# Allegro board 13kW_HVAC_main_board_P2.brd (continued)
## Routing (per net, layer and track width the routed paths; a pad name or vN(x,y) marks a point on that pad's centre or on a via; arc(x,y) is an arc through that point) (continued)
IPH_V+: length 102.6
  I_SAMPLING05 w0.508: v1(58.77,58.8) 58.7,59.02 59.76,61.54 59.76,70.92 55.07,80.27 39.65,87.22 36.92,93.59 36.84,96.22 38,98.54 43.02,102.75 46.78,105.81 46.85,105.88 50.89,111.63 50.89,117.12 55.11,121.33 66.56,121.33 70.63,125.39 J1.25
  BOTTOM w0.508: v1(58.77,58.8) C14.1 R41.2
IPH_W+: length 131
  TOP w0.381: v1(84.72,120.72) 84.64,120.81 84.64,120.83 82.28,123.19 77.24,123.19 73.24,127.18 73.24,128.77 v1(73.37,128.9)
  VCC02 w0.381: J1.22 65.76,129.23 67.6,131.07 71.95,131.07 73.24,129.77 73.24,129.03 v1(73.37,128.9)
  GND03 w0.508: v1(93.64,60.45) 93.53,61.28 88.96,64.91 88.73,67.24 92.92,75.63 95.53,78.23 v1(97.75,78.23)
  PWM04 w0.508: v1(84.72,120.72) 85.89,121.89 108.38,121.89 116.04,114.23 116.04,99.06 98.64,81.66 98.64,78.74 98.14,78.23 v1(97.75,78.23)
  BOTTOM w0.508: R85.1 C16.1 v1(93.64,60.45)
IU+: length 58.8
  BOTTOM w0.508: U3.12 74.64,123.91 C24.1 74.79,124.23 75.4,124.84 75.4,129.72 72.92,132.2 39.91,132.2 37.56,129.85 37.56,125.77 38.6,124.72 40.72,124.72 J1.3
IU-: length 49.5
  BOTTOM w0.508: R36.2 73.11,125.75 C24.2 74.64,126.07 74.64,129.41 72.61,131.44 40.22,131.44 38.32,129.54 38.32,126.08 38.92,125.48 39.64,125.48 40.15,125.99 J1.1
IU_OCP: length 9.6
  BOTTOM w0.508: R65.2 78.96,126.3 78.96,127.38 78.45,127.88 76.93,127.88 76.16,127.12 76.16,122.35 U3.13
IV+: length 132.2
  I_SAMPLING05 w0.508: J1.7 45.69,124.96 43.85,124.96 41.12,123.71 34.68,115.35 31.95,111.64 30.32,110.89 27.8,110.92 25.76,110.94 18.93,111.03 17.12,110.49 15.28,109.92 10.55,102.48 9.78,100.55 3.76,84.27 2.17,71.53 3,63.08 5.29,53.09 10.51,47.87 13.45,47.87 v1(17.36,48)
  BOTTOM w0.508: v1(17.36,48) 16.98,47.37 19.52,40.25 23.33,38.48 24.86,39.24 25.11,40 C23.1 25.87,41.02 26.13,41.52 U1.12
IV-: length 125.3
  I_SAMPLING05 w0.508: v1(18.13,46.99) 10.25,46.99 4.5,52.74 2.32,62.25 1.4,71.54 3.01,84.45 9.87,102.99 14.65,110.52 18.76,111.8 27.5,111.68 30.06,111.76 31.49,112.31 34.07,115.81 40.47,124.12 40.61,124.32 43.69,125.73 44.6,125.73 45.15,126.19 J1.5
  BOTTOM w0.508: v1(18.13,46.99) 20.28,41.02 21.3,40.51 R37.2
  BOTTOM w0.762: C23.2 R37.2
IV_OCP: length 9.3
  BOTTOM w0.508: U1.13 25.36,43.05 24.35,43.05 21.55,41.78 20.79,42.03 20.28,43.3 20.54,44.06 R64.2
IW+: length 163.4
  I_SAMPLING05 w0.508: v1(132.17,44.19) 132.34,46.15 132.32,46.83 132.91,47.91 135.43,49.45 137.92,54.75 138.13,55.45 139.57,67.51 137.17,86.28 133.76,96.96 133.41,97.71 130.93,102.36 125.69,110.78 122.94,114.35 119.19,118.88 112.37,124.88 109.44,127.46 104.85,130.55 100.33,130.55 99.57,131.31 90.07,131.32 75.85,131.32 74.97,132.2 54.89,132.2 54.12,131.43 54.12,128.44 52.85,127.17 J1.11
  BOTTOM w0.508: v1(132.17,44.19) 132.25,44.22 130.52,45.08 130.27,45.59 C39.1 U5.12
IW-: length 161.1
  I_SAMPLING05 w0.508: J1.9 50.38,126.69 51.58,127.88 51.58,129.97 54.57,132.96 75.28,132.96 76.16,132.08 90.07,132.08 99.06,132.07 100.04,132.07 100.79,131.31 105.09,131.31 110.67,127.55 119.74,119.41 125.91,111.95 133.93,98.94 137.92,86.45 140.43,68.41 139.64,60.36 138.97,55.24 136.07,48.61 133.86,47.6 v1(133.44,46.48)
  BOTTOM w0.508: C39.2 R143.2 v1(133.44,46.48)
IW_OCP: length 8.7
  BOTTOM w0.508: U5.13 128.74,44.83 131.64,43.49 131.94,42.78 131.28,41.28 130.27,41.02 R78.2
NETC4_2: length 10.3
  TOP w0.508: v1(61.94,38.22) PAD19.1
  BOTTOM w0.762: R55.2 R31.2 C4.2 66.37,40.24 Q5.6 v1(61.94,38.22)
  vias: v1(59.54,37.38) v1(59.92,36.62) v1(60.45,37.83) v1(60.83,37.07)
NETC5_2: length 10.2
  TOP w0.508: PAD20.1 v1(108.93,76.58)
  BOTTOM w0.762: R54.2 R30.2 C5.2 Q4.6 v1(108.93,76.58)
  vias: v1(109.74,75.13) v1(110.11,75.93) v1(110.76,74.54) v1(111.14,75.35)
NETC6_2: length 10
  TOP w0.762: v1(56.12,91.96) 56.18,92.39 v1(55.46,93.34)
  BOTTOM w0.762: R56.2 55.97,84.04 R34.2 56,85.75 C6.2 56.16,87.29 Q6.6 56.12,90.17 v1(56.12,91.96)
  vias: v1(55.46,94.23) v1(56.35,94.23) v1(56.35,93.34)
NETC7_1: length 55.2
  TOP w0.508: 46.48,70.81 46.14,70.92 PAD3.1 ; v1(38.7,17.39) 37.38,16.08 R1.2
  PWM04 w0.127: 88.06,47.9 87.63,47.9 88.06,47.9 ; 88.06,47.9 C9.1
  PWM04 w0.508: v1(38.7,17.39) 42.26,17.39 43.53,18.66 75.08,18.66 C7.1
  BOTTOM w0.508: Q2.9 44.45,78.09
  vias: v1(40.8,78.06) v1(41.09,77.37) v1(41.7,76.8) v1(42.21,75.72) v1(42.35,77.11) v1(42.65,74.72) v1(42.86,76.03) v1(43.1,73.71) v1(43.3,75.03) v1(43.49,76.3) v1(43.54,72.71) v1(43.75,74.02) v1(43.94,75.3) v1(43.93,71.89) v1(44.14,79.31) v1(44.14,76.62) v1(44.19,73.02) v1(44.25,78.01) v1(44.37,71.02) v1(44.46,74.37) v1(44.58,75.62) v1(44.58,72.21) v1(44.76,76.93) v1(44.81,70.02) v1(44.91,73.37) v1(45.05,71.27) v1(45.21,75.93) v1(45.25,74.75) v1(45.29,72.56) v1(45.32,68.94) v1(45.46,70.33) v1(45.69,73.75) v1(45.76,71.62) v1(45.77,67.94) v1(45.97,69.25) v1(46.08,72.94) v1(46.09,70.65) v1(46.28,66.85) v1(46.42,68.25) v1(46.55,72) v1(46.62,74.65) v1(46.6,69.5) v1(46.74,70.96) v1(46.73,65.85) v1(46.93,67.16) v1(47.07,73.65) v1(47.04,68.5) v1(47.24,69.81) v1(47.25,64.76) v1(47.36,71.27) v1(47.38,66.16) v1(47.53,75.11) v1(47.59,72.57) v1(47.69,68.81) v1(47.69,63.76) v1(47.87,70.12) v1(47.97,74.11) v1(47.9,65.07) v1(48.03,71.57) v1(48.31,69.12) v1(48.34,64.07) v1(48.49,73.03) v1(48.56,70.55) v1(48.52,65.32) v1(48.74,74.45) v1(48.94,72.03) v1(48.97,64.32) v1(49.01,69.55) v1(49.17,65.63) v1(49.26,73.38) v1(49.34,74.7) v1(49.39,68.74) v1(49.47,71.01) v1(49.61,64.63) v1(49.71,72.38) v1(49.79,65.94) v1(49.84,67.74) v1(49.91,70.01) v1(50.17,73.84) v1(50.23,71.36) v1(50.25,66.9) v1(50.3,69.2) v1(50.61,72.84) v1(50.68,70.36) v1(50.74,68.2) v1(50.7,65.9) v1(51.06,69.54) v1(51.14,71.82) v1(51.16,67.36) v1(51.59,70.82) v1(51.51,68.54) v1(51.6,66.36) v1(51.97,70) v1(51.92,67.7) v1(52.37,66.7) v1(52.42,69) v1(52.83,68.16) v1(53.28,67.16) v1(53.36,69.37) v1(53.8,68.37) v1(54.26,69.83) v1(54.21,67.53) v1(54.71,68.83) v1(55.03,70.17) v1(55.12,67.99) v1(55.48,69.17) v1(55.89,68.33) v1(55.94,70.63) v1(56.38,69.63) v1(56.8,68.79) v1(82.04,9.19) v1(82.04,7.92) v1(82.07,6.81) v1(82.07,5.54) v1(82.07,4.27) v1(82.03,3.39) v1(83.21,9.19) v1(83.21,7.92) v1(83.24,6.81) v1(83.24,5.54) v1(83.24,4.27) v1(83.2,3.39) v1(84.45,14.92) v1(84.47,13.97) v1(84.47,12.7) v1(84.47,11.43) v1(84.41,10.42) v1(84.41,9.15) v1(84.41,7.88) v1(84.44,6.77) v1(84.44,5.5) v1(84.44,4.23) v1(84.4,3.36) v1(85.05,94.27) v1(85.06,93.55) v1(85.02,92.88) v1(85.03,92.16) v1(85.05,91.46) v1(85.68,10.42) v1(85.68,9.15) v1(85.68,7.88) v1(85.67,3.36) v1(85.72,90.64) v1(85.75,89.63) v1(85.74,88.79) v1(85.78,87.77) v1(85.71,86.77) v1(85.74,85.75) v1(85.73,84.91) v1(85.76,83.89) v1(85.72,14.92) v1(86.15,94.25) v1(86.16,93.53) v1(86.11,92.86) v1(86.12,92.14) v1(86.14,91.44) v1(86.65,86.78) v1(86.68,85.77) v1(86.67,84.93) v1(86.7,83.91) v1(86.82,90.63) v1(86.85,89.61) v1(86.84,88.77) v1(86.87,87.75) v1(86.93,50.34) v1(86.96,49.5) v1(86.96,10.41) v1(86.96,9.14) v1(86.96,7.87) v1(86.94,3.36) v1(87,14.91) v1(87.35,94.26) v1(87.36,93.54) v1(87.4,51.44) v1(87.75,90.64) v1(87.79,89.63) v1(87.77,88.79) v1(87.74,86.77) v1(87.78,85.75) v1(87.76,84.91) v1(87.81,87.77) v1(87.8,83.89) v1(87.82,50.07) v1(88.24,51.14) v1(88.27,14.91) v1(88.25,13.91) v1(88.25,12.64) v1(88.25,11.37) v1(88.23,10.41) v1(88.23,9.14) v1(88.23,7.87) v1(88.2,6.9) v1(88.2,5.63) v1(88.2,4.36) v1(88.21,3.35) v1(88.44,94.24) v1(88.46,93.52) v1(88.76,49.69) v1(88.85,90.63) v1(88.88,89.61) v1(88.87,88.77) v1(88.9,87.75) v1(89.18,50.75) v1(89.45,13.83) v1(89.45,12.56) v1(89.45,11.29) v1(89.42,6.9) v1(89.42,5.63) v1(89.42,4.36) v1(89.54,14.91) v1(89.5,10.41) v1(89.5,9.14) v1(89.5,7.87) v1(89.65,94.25) v1(89.66,93.53) v1(89.62,92.86) v1(89.63,92.14) v1(89.65,91.44) v1(89.67,49.17) v1(89.75,90.63) v1(89.78,89.62) v1(89.77,88.77) v1(89.8,87.76) v1(90.1,50.24) v1(90.54,46.33) v1(90.62,48.79) v1(90.75,94.23) v1(90.76,93.51) v1(90.71,92.84) v1(90.73,92.12) v1(90.74,91.42) v1(90.77,10.41) v1(90.77,9.14) v1(90.77,7.87) v1(90.84,90.61) v1(90.88,89.6) v1(90.86,88.76) v1(90.81,14.91) v1(90.9,87.74) v1(90.96,47.4) v1(91.04,49.86) v1(91.42,48.39) v1(91.48,45.95) v1(91.89,49.48) v1(91.87,10.44) v1(91.87,9.17) v1(91.87,7.9) v1(91.94,94.23) v1(91.95,93.51) v1(91.97,92.81) v1(91.98,92.09) v1(91.99,90.66) v1(91.9,47.01) v1(92,91.39) v1(92.02,89.64) v1(92.01,88.8) v1(92.04,87.79) v1(92.36,48.01) v1(92.4,45.43) v1(92.83,49.1) v1(92.82,46.5) v1(93.04,94.22) v1(93.05,93.5) v1(93.08,90.64) v1(93.17,92.37) v1(93.14,91.54) v1(93.12,89.63) v1(93.1,88.78) v1(93.14,87.77) v1(93.28,47.49) v1(93.75,48.59) v1(94.01,94.24) v1(94.02,93.52) v1(94.28,90.66) v1(94.22,47.11) v1(94.36,92.39) v1(94.33,91.55) v1(94.31,89.64) v1(94.3,88.8) v1(94.33,87.79) v1(94.69,48.2) v1(94.91,94.25) v1(94.92,93.53) v1(95.37,90.64) v1(95.39,88.78) v1(95.45,92.37) v1(95.43,91.54) v1(95.4,89.63) v1(96.01,94.23) v1(96.02,93.51) v1(96.25,48.78) v1(96.7,49.69) v1(96.77,46.22) v1(97.11,94.21) v1(97.12,93.49) v1(97.1,92.8) v1(97.11,92.08) v1(97.13,91.38) v1(97.23,47.21) v1(97.41,48.19) v1(97.94,49.24) v1(98.2,94.19) v1(98.22,93.47) v1(98.19,92.78) v1(98.21,92.06) v1(98.22,91.36) v1(99.4,94.19) v1(99.41,93.47) v1(99.42,91.37) v1(100.48,94.19) v1(100.5,93.46) v1(100.51,91.35)
NETC17_2: length 5.3
  TOP w0.762: v2(42.17,90.97) 42.11,91.02 C18.2 C17.2 R66.2
  BOTTOM w0.762: v2(42.17,90.97) U2.1
NETC25_1: length 4.4
  BOTTOM w0.762: U2.2 42.21,92.24 C25.1 40.78,92.18 R69.1 40.71,92.24 R67.2
NETC26_1: length 8.9
  TOP w0.508: C27.1 47.58,94.45 C28.1 C26.1 ; C27.1 49.84,94.45 v1(50.27,94.88) ; C27.1 48.97,96.32 R68.1
  BOTTOM w0.508: U2.5 v1(50.27,94.88)
  BOTTOM w0.762: U2.5 50.18,94.86
NETC30_1: length 19.7
  BOTTOM w0.254: R75.1 116.68,114.7 112.99,114.68 112.44,114.12 112.44,107.81 112.99,107.44 U4.14
  BOTTOM w0.508: U4.10 115.57,112.5 116.33,113.25 116.33,113.25 116.36,113.28 C30.1
  BOTTOM w0.762: R72.2 R75.1 C30.1
NETC32_1: length 1.3
  BOTTOM w0.762: R73.1 C32.1
NETC34_2: length 5.7
  TOP w0.762: R83.2 C34.2 C36.2 v1(68.87,25.95)
  BOTTOM w0.762: v1(68.87,25.95) U7.1
NETC35_1: length 80.2
  TOP w1.016: CN2.1 11.39,88.77 9.87,83.05 7.76,81.14 C35.1
  TOP w1.524: C35.1 CN1.1
  VCC02 w1.27: CN2.1 11.02,86.78 9.52,82.26 C35.1
  PWM04 w1.27: CN1.1 C35.1
  I_SAMPLING05 w1.27: CN1.1 C35.1 9.62,82.93 11.14,88.18 CN2.1
  BOTTOM w1.524: CN2.1 12.92,90.67 9.74,85.47 10,82.42 C35.1 CN1.1
NETC38_1: length 20.1
  I_SAMPLING05 w0.508: v1(117.22,101.2) 117.3,101.97 117.69,102.36 117.69,108.45 118.99,109.75 118.99,110.25 119.85,111.12 v1(119.85,111.25)
  BOTTOM w0.508: v1(119.85,111.25) 119.85,110.33 119.34,109.83 R70.1
  BOTTOM w0.762: v1(117.22,101.2) 117.22,101.97 R81.2 C38.1 C40.1 116.19,106.15 U4.15
NETC48_1: length 5.1
  BOTTOM w0.762: R86.2 R90.1 C48.1 U7.2
NETC49_1: length 8.5
  TOP w0.508: R89.1 60.76,29.77 60.94,29.95 ; C50.1 C51.1 C49.1
  TOP w0.762: v1(61.58,31.87) C50.1 R89.1
  BOTTOM w0.762: v1(61.58,31.87) U7.5
NETC55_2: length 6
  TOP w0.762: v1(113.81,89.56) C56.2 C55.2 R99.2
  BOTTOM w0.762: v1(113.81,89.56) U9.1
NETC58_1: length 15.8
  BOTTOM w0.762: Q7.C R98.2
  BOTTOM w1.016: R98.2 124.3,88.13 122.9,88.64 122.52,90.04 122.77,91.31 C61.1 ; C61.1 C59.1 D6.2 ; C61.1 C58.1
NETC58_2: length 8.9
  TOP w1.016: v1(122.27,94.99) 123.31,94.86 T1.4
  BOTTOM w1.016: v1(122.27,94.99) C58.2 C63.1
NETC60_2: length 10
  TOP w0.508: T1.3 124.93,99.69 125.73,99.69 129.12,101.72 129.25,102.36 127.66,105.24
NETC65_1: length 2.1
  TOP w0.381: U8.3 118.75,109.72
  TOP w0.508: C65.1 R100.2
NETC66_1: length 2.9
  TOP w0.381: U8.5 C66.1 R105.1
NETC68_1: length 4.5
  BOTTOM w0.762: R101.2 R103.1 C68.1 U9.2
NETC70_1: length 7.8
  TOP w0.508: v1(113.78,80.48) 113.71,81.23 C71.1 ; C71.1 C72.1 C70.1 ; C71.1 114.99,81.31 R102.1
  BOTTOM w0.762: v1(113.78,80.48) U9.5
NETC74_1: length 20
  BOTTOM w0.508: U10.10 17.03,83.75 16.08,83.98 C74.1 15.71,84.65 14.52,84.09 R112.1 ; R112.1 R110.2 ; R112.1 14.38,83.92 16.3,79.81 17.2,79.81 22.64,82.77 22.73,83.59 U10.14
NETC77_1: length 12.5
  TOP w0.711: C77.1 102.24,118 R115.2
  TOP w0.762: Q8.C 107.57,118.42 106.9,119.09 v1(103.61,119.09) R115.2
  BOTTOM w0.762: C78.1 103.61,118.18 v1(103.61,119.09) ; C78.1 101.73,117.95 D10.2 ; C78.1 105.13,117.95 C80.1
NETC77_2: length 4.8
  TOP w0.762: T2.4 99.41,114.55 C83.1 C77.2
NETC82_1: length 17.1
  PWM04 w0.508: v1(17.4,87.86) 18.08,88.55 v1(26.44,88.55)
  BOTTOM w0.508: R108.1 v1(17.4,87.86) ; U10.15 22.66,86.76 C84.1 C82.1 R116.2 26.04,89.41 v1(26.44,88.55)
NETC89_1: length 14.2
  I_SAMPLING05 w0.508: v1(102.02,15.81) v1(107.02,12.61)
  BOTTOM w0.508: R121.1 106.03,13.25 106.29,13.25 106.63,13.59 U11.10 ; R121.1 C89.1 ; R121.1 R119.2 v1(107.02,12.61) ; U11.14 v1(102.02,15.81)
NETC93_1: length 18.6
  TOP w0.762: v1(13.65,76.09) Q9.C R126.2
  BOTTOM w0.711: 12.97,69.84 12.2,70.59 D16.2
  BOTTOM w0.762: 12.97,69.84 16.09,69.87 C93.1 ; v1(13.65,76.09) C95.1 ; C95.1 13.43,74.04 13.43,72.51 D16.2 ; C95.1 C97.1
NETC93_2: length 5.4
  TOP w1.27: v1(17.19,66.64) T3.4
  BOTTOM w0.762: C93.2 v1(17.19,66.64) 18.32,67.77 C102.1
NETC96_1: length 24.3
  PWM04 w0.762: v1(100.71,12.42) 100.71,15.11 95.16,17.7 v1(94.66,19.15) 95.44,20.85
  BOTTOM w0.508: v1(94.66,19.15) 95.6,20.95 95.6,20.95 95.9,21.26 96.1,21.33 96.74,21.33 R127.2 C96.1 C99.1 100.49,20.12 102.1,19.27 102.28,18.65 U11.15 ; v1(100.71,12.42) R117.1
NETC104_2: length 258.5
  TOP w1.016: v1(87.47,118.23) 87.51,116.65 89.53,114.71 T2.3 ; T4.3 85.7,24.11 84.17,25.65 83.28,28.32 74.26,37.46 v1(74.26,44.06)
  TOP w1.27: T3.3 v1(13.52,56.89)
  GND03 w1.016: v1(87.47,118.23) 87.47,118.5 87.72,118.76 89.13,120.16 107.63,120.16 111.72,116.07 111.72,102.54 v1(114.26,100)
  PWM04 w1.016: v1(51.27,79.96) 51.15,80.08 49.01,80.08 43.12,85.97 35.02,85.97 32.98,83.94 28.19,83.94 25.1,85.97 22.06,85.85 14.82,81.91 10.96,75.42 10.41,69.12 7.46,66.16 7.46,62.95 8.87,61.54 v1(13.52,56.89)
  BOTTOM w0.762: C104.2 R128.1 73.24,64.92 73.24,63.88 72.93,63.56 R134.2 C110.1 ; 80.75,63.69 77.48,63.69
  BOTTOM w1.016: v1(74.26,44.06) 74.57,44.38 C104.2 75.53,64.96 76.9,64.07 76.96,64 76.99,64 77.48,63.69 ; 80.75,63.69 105.85,88.79 105.86,88.79 111.98,94.92 111.98,97.56 114.26,99.84 v1(114.26,100) ; v1(51.27,79.96) 55.82,79.96 65.88,69.9 65.88,67.31 69.62,63.56 C110.1
NETC108_1: length 2.8
  BOTTOM w0.381: 79.38,67.35 U12.5
  BOTTOM w0.508: C108.1 79.38,67.35
  BOTTOM w0.762: C108.1 R131.1
NETC109_1: length 4.1
  BOTTOM w0.305: 77.18,72.48 U12.3
  BOTTOM w0.508: R129.2 77.18,72.48
  BOTTOM w0.762: R129.2 74.6,73.57 C109.1
NETC110_2: length 3.3
  BOTTOM w0.762: RJ1.2 71.93,66.32 R134.1 C110.2
NETC112_1: length 17.1
  TOP w0.762: Q10.C C113.1 ; C113.1 R138.2 ; C113.1 C114.1 102.83,28.37 102.8,28.45 102.8,28.53 102.69,28.82 102.62,28.85 102.58,28.95 102.57,28.97 102.35,29.1 102.33,29.16 100.88,29.83 99.54,29.92 D22.2 97.65,29.69 96.33,26.92 C112.1
NETC112_2: length 4.7
  TOP w0.762: T4.4 C112.2 C116.1
NETC121_2: length 4.3
  BOTTOM w0.508: 117.18,109.96 R70.2
  BOTTOM w0.762: C121.2 R70.2 ; U4.12 117.18,109.96
NETC122_2: length 3.9
  BOTTOM w0.508: C122.2 17.48,85.53 R108.2 18.81,86.01 19.73,84.03 U10.12
NETC123_2: length 5.4
  BOTTOM w0.254: C123.2 102.47,14.18 103.05,14.57 103.06,14.58 103.07,14.58 103.11,14.61 103.4,14.7 103.71,14.81 104.23,14.81 104.71,14.95 U11.12
  BOTTOM w0.762: R117.2 101.85,14.16 C123.2
NETCN2_5: length 16.3
  I_SAMPLING05 w1.27: L1.4 29.96,89.23 27.1,92.08 22.57,96.02 CN2.5
NETCN2_6: length 29.8
  TOP w0.457: L1.3 19.7,94.66 17.87,94.66 16.2,96.34 CN2.6
  PWM04 w0.457: CN2.6 16.19,96.34 16.5,95.68 18.4,94.46 L1.3
  I_SAMPLING05 w0.457: L1.3 19.7,94.66 17.92,94.66 17.79,94.79 17.77,94.79 16.2,96.36 CN2.6
  BOTTOM w0.457: L1.3 19.7,94.66 17.9,94.66 16.2,96.36 CN2.6
NETCON3_1: length 4.9
  BOTTOM w0.508: CON3.3 38.52,25.47 R4.2
  vias: v1(35.28,45.44) v1(35.86,45.7) v1(35.82,44.28) v1(36.36,43.13) v1(36.43,45.97) v1(36.4,44.55) v1(36.97,44.82) v1(36.93,43.4) v1(36.9,41.11) v1(37.05,46.79) v1(36.99,46.18) v1(37.48,40.04) v1(37.57,45.68) v1(37.53,45.03) v1(37.51,43.67) v1(37.93,41.59) v1(37.99,38.77) v1(37.98,36.03) v1(38.09,47.27) v1(38.07,43.88) v1(38.13,44.48) v1(38.15,31.14) v1(38.49,37.7) v1(38.51,40.52) v1(38.6,46.16) v1(38.64,43.38) v1(38.63,30.1) v1(39.02,39.25) v1(39.02,36.52) v1(39.06,29.13) v1(39.16,44.97) v1(39.1,35.57) v1(39.2,42.18) v1(39.41,31.73) v1(39.52,38.18) v1(39.59,34.53) v1(39.68,43.86) v1(39.78,41.11) v1(39.9,30.69) v1(40.02,36) v1(40.02,33.57) v1(40.19,37.01) v1(40.24,42.66) v1(40.29,39.84) v1(40.33,29.72) v1(40.48,32.34) v1(40.51,34.96) v1(40.75,41.56) v1(40.79,38.77) v1(40.94,34) v1(40.96,31.3) v1(41.31,40.36) v1(41.41,37.58) v1(41.4,30.34) v1(41.75,32.93) v1(41.83,39.26) v1(41.86,29.19) v1(42.23,31.89) v1(42.31,38) v1(42.35,28.15) v1(42.66,30.93) v1(42.78,33.41) v1(42.78,29.62) v1(42.78,27.18) v1(43.27,32.38) v1(43.27,28.58) v1(43.7,31.41) v1(43.7,27.61) v1(44.05,34) v1(44.53,32.97) v1(44.96,32)
NETCON4_1: length 5.5
  TOP w0.762: R5.2 131.41,59.94 CON4.4
  vias: v1(117.33,52.33) v1(117.63,53.44) v1(118.19,54.64) v1(118.13,51.79) v1(118.67,52.96) v1(118.65,52.19) v1(118.7,55.74) v1(119.19,53.34) v1(119.17,51.9) v1(119.26,56.94) v1(119.23,54.15) v1(119.78,58.04) v1(119.74,55.26) v1(119.73,54.49) v1(119.71,53.05) v1(119.75,51.63) v1(120.25,54.2) v1(120.29,52.78) v1(120.34,59.24) v1(120.3,56.45) v1(120.32,51.36) v1(120.74,57.58) v1(120.85,60.34) v1(120.82,53.93) v1(120.86,52.51) v1(121.39,58.79) v1(121.4,53.66) v1(121.5,61.53) v1(121.56,55.86) v1(121.89,59.86) v1(122.01,56.99) v1(122.41,61.11) v1(122.66,58.2) v1(122.6,55.38) v1(123.05,56.51) v1(123.15,59.27) v1(123.45,65.43) v1(123.63,60.54) v1(123.69,57.72) v1(123.93,66.46) v1(124.19,58.79) v1(124.39,67.41) v1(124.51,61.06) v1(124.71,64.84) v1(124.76,59.96) v1(124.99,62.1) v1(125.2,65.87) v1(125.45,63.05) v1(125.43,60.63) v1(125.66,66.82) v1(125.75,64.35) v1(125.79,59.47) v1(125.91,61.67) v1(126.23,65.39) v1(126.37,62.62) v1(126.69,66.34) v1(127.01,63.76) v1(127.5,64.8) v1(127.62,67.28) v1(127.96,65.75) v1(128.1,68.31) v1(128.17,63.34) v1(128.57,69.26) v1(128.54,66.85) v1(128.65,64.37) v1(129.02,67.88) v1(129.12,65.33) v1(129.49,68.84) v1(129.44,62.75) v1(129.92,63.78) v1(130.38,64.74)
NETCON5_1:
  vias: v1(53.79,113.92) v1(53.79,112.9) v1(54.85,113.9) v1(54.85,112.89) v1(55.99,113.9) v1(55.99,112.89) v1(57.13,116.47) v1(57.13,115.07) v1(57.23,113.84) v1(57.23,112.44) v1(57.23,111.3) v1(57.23,109.9) v1(58.18,116.45) v1(58.18,115.05) v1(58.29,113.82) v1(58.29,112.43) v1(58.29,111.28) v1(58.29,109.89) v1(59.33,116.45) v1(59.33,115.05) v1(59.43,113.82) v1(59.43,112.43) v1(59.43,111.28) v1(59.43,109.89) v1(60.04,115.82) v1(60.16,114.55) v1(60.74,113.73) v1(60.74,112.71) v1(61.8,113.71) v1(61.8,112.69) v1(62.94,113.71) v1(62.94,112.69) v1(63.79,112.12) v1(63.78,110.77) v1(63.78,109.77) v1(64.97,112.14) v1(65.13,110.83) v1(65.18,109.91) v1(66.9,109.91) v1(68.23,109.91) v1(69.4,112.22) v1(69.4,110.83) v1(69.44,109.91) v1(69.66,113.37) v1(70.72,110.83) v1(70.77,109.91) v1(71.47,113.64) v1(71.47,113) v1(71.47,112.37) v1(71.47,111.73) v1(71.94,110.83) v1(71.95,109.91) v1(72.74,113.64) v1(72.74,113) v1(72.74,112.37) v1(72.74,111.73) v1(73.26,110.83) v1(73.27,109.91) v1(74.01,113.64) v1(74.01,113) v1(74.01,112.37) v1(74.01,111.73) v1(74.48,110.83)
NETD1_2: length 2.2
  BOTTOM w0.762: R24.1 D1.2
NETD1_2_2: length 2.2
  TOP w0.762: R24_2.1 D1_2.2
NETD2_2: length 2.2
  BOTTOM w0.762: R25.1 D2.2
NETD3_2: length 2.2
  BOTTOM w1.27: R26.1 D3.2
NETD4_1: length 3.5
  TOP w0.762: R140.2 109.49,102.92 108.11,101.54 D4.1
NETD4_2: length 4.5
  TOP w1.016: D5.1 D4.2
NETD6_1: length 7.1
  TOP w1.016: T1.6 v1(132.04,94.61)
  BOTTOM w1.016: D6.1 D8.2 131.2,95.38 v1(132.04,94.61)
NETD7_2: length 6.6
  BOTTOM w0.762: D7.2 R98.1 128.75,85.1 Q7.B
NETD10_1: length 4.6
  TOP w0.762: v1(98.01,119.12) 98.01,118.26 T2.6
  BOTTOM w0.762: v1(98.01,119.12) 98.27,118.98 D10.1 98.27,115.67 D12.2
NETD11_2: length 6
  TOP w0.711: R115.1 105.08,117.29 104.3,116.51 D11.2
  TOP w0.762: R115.1 106.49,118 107.19,117.3 Q8.B
NETD14_1: length 6.8
  TOP w1.016: D14.1 v1(32.43,81.58)
  BOTTOM w0.762: v1(32.43,81.58) 33.11,81.43 34.1,79.35 33.82,78.66 R141.2
NETD14_2: length 3.7
  TOP w1.016: D15.1 40.35,82.82 D14.2
NETD16_1: length 5.2
  TOP w1.27: T3.6 v1(13.05,68.58)
  BOTTOM w0.762: D18.2 13.44,68.58 v1(13.05,68.58) 12.19,67.72 D16.1
NETD17_2: length 3
  TOP w0.762: Q9.B R126.1 D17.2
NETD20_1: length 5.6
  TOP w1.016: D20.1 90.1,36.04 R142.2
NETD20_2: length 3.8
  TOP w1.016: D20.2 89.87,41.11 D21.1
NETD22_1: length 4.5
  TOP w0.762: D22.1 D24.2 T4.6
NETD23_2: length 2.9
  TOP w0.762: Q10.B R138.1 D23.2
NETD26_1: length 1.7
  BOTTOM w1.27: D27.2 D26.1
NETD27_1: length 1.7
  BOTTOM w1.27: D28.2 D27.1
NETPAD8_1:
  vias: v1(28.49,65.41) v1(29.03,64.26) v1(29.52,63.34) v1(30.05,62.18) v1(30.51,61.26) v1(31.33,60.18) v1(31.82,59.2) v1(31.97,66.87) v1(32.06,60.52) v1(32.27,58.16) v1(32.5,65.72) v1(32.5,59.52) v1(32.67,57.15) v1(32.77,67.24) v1(32.99,64.79) v1(33,58.51) v1(33.18,56.04) v1(33.14,50.06) v1(33.21,61.05) v1(33.31,66.09) v1(33.53,63.64) v1(33.67,60.01) v1(33.68,48.91) v1(33.7,57.63) v1(33.74,54.84) v1(33.71,50.33) v1(33.8,65.17) v1(33.99,62.72) v1(34.15,59.04) v1(34.22,56.52) v1(34.26,53.74) v1(34.29,50.59) v1(34.25,49.17) v1(34.21,47.76) v1(34.33,64.02) v1(34.44,61.62) v1(34.6,52.78) v1(34.79,63.09) v1(34.78,55.33) v1(34.79,48.02) v1(34.89,60.58) v1(34.85,58.17) v1(34.87,50.86) v1(34.83,49.44) v1(35,51.83) v1(35.29,54.22) v1(35.34,62.04) v1(35.37,59.61) v1(35.39,57.01) v1(35.36,48.29) v1(35.4,49.71) v1(35.52,50.72) v1(35.64,53.26) v1(35.79,61) v1(35.93,55.86) v1(35.94,48.56) v1(36.08,58.73) v1(36.04,52.31) v1(36.07,49.52) v1(36.27,60.03) v1(36.46,54.71) v1(36.55,51.2) v1(36.59,48.42) v1(36.61,57.58) v1(36.81,53.75) v1(36.98,59.16) v1(37.15,56.43) v1(37.19,52.85) v1(37.11,50.01) v1(37.51,58) v1(37.69,55.28) v1(37.63,48.9) v1(37.72,51.69) v1(38.05,56.85) v1(38.03,54.32) v1(38.26,50.54) v1(38.41,53.41) v1(38.59,55.7) v1(38.8,49.39) v1(38.94,54.74) v1(38.95,52.26) v1(39.31,53.84) v1(39.48,51.11) v1(40.02,49.96) v1(40.69,48.51) v1(41.17,47.48) v1(41.72,46.32) v1(42.2,45.28) v1(42.58,46.78) v1(42.69,44.2) v1(43.07,45.75) v1(43.17,43.17) v1(43.56,44.67) v1(43.66,42.13) v1(44.05,46.22) v1(44.04,43.64) v1(44.06,41.16) v1(44.57,45.13) v1(44.52,42.6) v1(44.92,41.63) v1(45.05,44.1) v1(45.39,38.24) v1(45.45,45.58) v1(45.53,43.06) v1(45.94,44.54) v1(45.93,42.09) v1(45.94,37.08) v1(46.36,41.09) v1(46.31,38.67) v1(46.42,43.5) v1(46.42,36.04) v1(46.82,42.53) v1(46.87,40.09) v1(46.86,37.51) v1(46.94,34.96) v1(47.28,41.52) v1(47.35,39.06) v1(47.34,36.47) v1(47.42,33.92) v1(47.79,40.52) v1(47.83,35.4) v1(47.9,37.89) v1(47.91,32.88) v1(48.27,39.49) v1(48.38,36.86) v1(48.31,34.36) v1(48.45,31.68) v1(48.79,33.33) v1(48.82,38.32) v1(48.91,35.77) v1(48.93,30.65) v1(49.3,37.29) v1(49.39,34.73) v1(49.37,32.11) v1(49.79,36.21) v1(49.87,33.7) v1(49.85,31.08) v1(50.28,35.18) v1(50.41,32.5) v1(50.68,27.28) v1(50.76,34.14) v1(50.9,31.46) v1(51.33,32.92) v1(51.44,30.3) v1(51.56,27.72) v1(51.82,31.89) v1(51.93,29.26) v1(52.36,30.73) v1(52.45,28.17) v1(52.85,29.69) v1(53.33,28.61)
NETPAD10_1:
  vias: v1(105.48,35.89) v1(105.77,36.57) v1(106.16,37.54) v1(106.29,35.58) v1(106.58,36.2) v1(106.7,38.69) v1(106.97,37.16) v1(107.11,39.64) v1(107.57,40.73) v1(107.51,38.31) v1(107.92,39.26) v1(108.08,41.75) v1(108.47,40.31) v1(108.51,42.74) v1(108.73,43.84) v1(108.98,41.33) v1(109.26,44.99) v1(109.41,42.32) v1(109.63,43.42) v1(109.69,39.74) v1(109.8,46.14) v1(110.02,34.64) v1(110.16,44.57) v1(110.2,40.76) v1(110.34,47.29) v1(110.37,35.39) v1(110.63,41.75) v1(110.7,45.72) v1(110.85,48.18) v1(110.85,42.85) v1(110.84,39.2) v1(110.91,36.54) v1(111.24,46.87) v1(111.3,49.05) v1(111.38,44) v1(111.33,40.17) v1(111.45,37.61) v1(111.57,38.86) v1(111.75,47.76) v1(111.78,41.21) v1(111.92,45.15) v1(112,42.31) v1(112.01,39.86) v1(112.2,48.63) v1(112.46,46.3) v1(112.51,43.42) v1(112.51,40.87) v1(112.74,49.78) v1(112.97,47.19) v1(113.07,44.62) v1(113.03,41.83) v1(113.28,50.93) v1(113.42,48.06) v1(113.59,45.72) v1(113.55,42.94) v1(113.68,59.06) v1(113.81,52.08) v1(113.96,49.21) v1(114.09,57.57) v1(114.16,60.1) v1(114.1,46.6) v1(114.11,44.13) v1(114.49,53.53) v1(114.59,58.67) v1(114.5,50.36) v1(114.57,47.52) v1(114.65,61.14) v1(114.6,56.09) v1(114.62,45.24) v1(114.97,54.56) v1(115.07,59.7) v1(115.08,57.12) v1(115.03,51.51) v1(115.09,48.63) v1(115.13,62.06) v1(115.13,46.12) v1(115.55,60.74) v1(115.59,58.19) v1(115.51,55.73) v1(115.61,63.07) v1(115.65,49.82) v1(115.61,47.04) v1(116.05,64.1) v1(116.04,61.67) v1(116.07,59.23) v1(115.99,56.76) v1(116.16,50.93) v1(116.13,48.14) v1(116.53,65.14) v1(116.53,62.64) v1(116.56,60.26) v1(116.5,57.83) v1(116.68,49.34) v1(116.6,47.36) v1(116.97,63.67) v1(116.99,58.86) v1(117.07,66.3) v1(117.05,61.19) v1(117.14,48.51) v1(117.17,47.09) v1(117.2,50.45) v1(117.45,64.71) v1(117.47,59.9) v1(117.55,67.34) v1(117.67,49.66) v1(117.71,48.24) v1(117.75,46.82) v1(117.99,65.88) v1(117.96,60.83) v1(118.06,68.41) v1(118.25,49.39) v1(118.29,47.97) v1(118.33,46.55) v1(118.47,66.91) v1(118.42,64.16) v1(118.55,69.44) v1(118.82,49.12) v1(118.86,47.7) v1(118.97,68.01) v1(118.96,65.32) v1(119.03,70.48) v1(119.34,63.73) v1(119.46,69.05) v1(119.44,66.36) v1(119.4,48.86) v1(119.59,71.7) v1(119.88,64.89) v1(119.94,70.08) v1(120.07,72.74) v1(120.06,67.59) v1(120.36,65.93) v1(120.51,71.27) v1(120.54,68.63) v1(120.61,73.9) v1(120.89,69.64) v1(120.97,67.19) v1(120.99,72.31) v1(121.1,74.94) v1(121.48,70.72) v1(121.45,68.23) v1(121.53,73.47) v1(121.61,76) v1(121.88,69.26) v1(121.96,71.75) v1(122.02,74.51) v1(122.4,70.29) v1(122.52,75.61) v1(122.88,71.32) v1(123.71,75.07) v1(124.62,74.68)
NETPAD11_1:
  vias: v1(50.84,107.44) v1(50.87,106.45) v1(50.91,105.28) v1(50.93,104.28) v1(52.12,105.29) v1(52.12,104.27) v1(53.26,105.29) v1(53.26,104.27) v1(54.54,105.29) v1(54.54,104.28) v1(54.64,107.42) v1(54.64,106.4) v1(55.69,105.29) v1(55.69,104.28) v1(55.78,107.42) v1(55.78,106.4) v1(57,105.28) v1(57.03,104.28) v1(57.1,107.4) v1(57.12,106.41) v1(58.15,105.28) v1(58.17,104.28) v1(58.24,107.4) v1(58.27,106.41) v1(59.29,105.28) v1(59.38,107.4) v1(59.32,104.28) v1(59.41,106.41) v1(60.59,107.41) v1(60.59,106.4) v1(60.5,105.29) v1(60.5,104.27) v1(61.64,105.29) v1(61.64,104.27) v1(61.73,107.41) v1(61.73,106.4) v1(62.92,105.29) v1(62.92,104.28) v1(63.02,107.42) v1(63.02,106.4) v1(64.07,105.29) v1(64.07,104.28) v1(65.19,105.33) v1(65.19,104.31) v1(66.23,107.39) v1(66.29,106.41) v1(66.28,105.3) v1(66.3,104.31) v1(67.58,107.04) v1(67.64,106.06) v1(67.63,104.94) v1(67.66,103.95) v1(68.72,107.04) v1(68.78,106.06) v1(68.77,104.94) v1(68.8,103.95) v1(69.87,107.04) v1(69.93,106.06) v1(69.92,104.94) v1(69.94,103.95) v1(71.05,107.02) v1(71.11,106.04) v1(71.12,104.96) v1(72.19,107.02) v1(72.25,106.04) v1(73.48,107.03) v1(74.62,107.03) v1(75.98,108.48) v1(75.98,107.13) v1(76.03,110.89) v1(76.03,109.75) v1(76.55,113.56) v1(76.55,112.92) v1(76.55,112.29) v1(76.55,111.65) v1(77.25,110.89) v1(77.25,109.75) v1(77.25,108.48) v1(77.25,107.13) v1(77.82,113.56) v1(77.82,112.92) v1(77.82,112.29) v1(77.82,111.65) v1(78.57,110.89) v1(78.57,109.75) v1(78.52,108.48) v1(78.52,107.13) v1(79.09,113.56) v1(79.09,112.92) v1(79.09,112.29) v1(79.09,111.65) v1(79.79,110.89) v1(79.79,109.75) v1(79.79,108.48) v1(79.79,107.13) v1(79.79,106.14) v1(80.78,108.44) v1(80.77,107.09) v1(80.78,106.09) v1(80.83,110.85) v1(80.83,109.71) v1(81.79,108.35) v1(81.79,107) v1(81.79,106) v1(81.84,110.76) v1(81.84,109.62) v1(83.06,110.76) v1(83.06,109.62) v1(83.06,108.35) v1(83.06,107) v1(83.06,106) v1(84.38,110.76) v1(84.38,109.62) v1(84.33,108.35) v1(84.33,107) v1(84.33,106) v1(85.6,110.76) v1(85.6,109.62) v1(85.6,108.35) v1(85.6,107) v1(85.6,106) v1(86.69,109.89) v1(86.69,108.62) v1(86.69,107.27) v1(86.69,106.27) v1(86.69,110.69) v1(87.77,108.64) v1(87.77,107.3) v1(87.77,106.3) v1(87.82,110.66) v1(87.82,109.91) v1(88.91,110.69) v1(88.91,109.88) v1(88.91,108.61) v1(88.91,107.27) v1(88.91,106.27) v1(89.55,111.02) v1(90.09,107.21) v1(90.09,106.32) v1(90.62,111) v1(91.13,107.24) v1(91.13,106.35) v1(91.76,111.03) v1(92.4,107.24) v1(92.4,106.35) v1(92.9,111.03) v1(93.44,107.29) v1(93.44,106.4) v1(93.97,111.05) v1(94.71,107.29) v1(94.71,106.4) v1(94.92,111.03)
NETPAD21_1: length 8.8
  BOTTOM w0.508: R85.2 96.74,60.14 96.74,60.7 96.51,60.93 95.49,61.54 94.76,61.95 94.6,62.85 95.96,65.83 96.24,65.9 96.78,65.9 97.21,65.7
  vias: v1(97.92,62.01) v1(98.43,62.9) v1(98.82,61.59) v1(98.94,63.79) v1(99.32,62.48) v1(99.45,64.68) v1(99.83,63.37) v1(99.95,65.57) v1(100.26,62.08) v1(100.34,64.26) v1(100.43,66.55) v1(100.77,62.97) v1(100.81,67.37) v1(100.85,65.15) v1(101.29,68.36) v1(101.28,63.86) v1(101.33,66.13) v1(101.67,69.21) v1(101.7,66.95) v1(101.78,64.75) v1(102.03,63.49) v1(102.15,70.2) v1(102.18,67.94) v1(102.26,65.73) v1(102.56,68.79) v1(102.54,64.38) v1(102.64,66.55) v1(102.88,74.27) v1(102.91,70.88) v1(103.04,69.78) v1(103.02,65.37) v1(103.12,67.54) v1(103.38,75.36) v1(103.46,74.01) v1(103.39,66.18) v1(103.48,63.98) v1(103.5,70.62) v1(103.5,68.39) v1(103.85,76.34) v1(103.87,67.17) v1(103.96,75.09) v1(103.98,69.38) v1(103.95,64.97) v1(104.17,76.99) v1(104.21,70.3) v1(104.25,68.03) v1(104.33,65.79) v1(104.44,76.08) v1(104.77,76.75) v1(104.73,69.01) v1(104.8,70.04) v1(104.81,66.77) v1(105.19,67.63) v1(105.46,69.73) v1(105.67,68.61) v1(105.83,70.55) v1(106.04,69.47) v1(106.22,71.45) v1(106.42,70.29) v1(106.7,72.43) v1(106.81,71.19) v1(107.2,73.52) v1(107.29,72.17) v1(107.68,74.5) v1(107.79,73.25) v1(107.97,75.21) v1(108.27,74.24)
NETPAD23_1: length 8.6
  BOTTOM w0.508: R42.1 75.55,87.42 75.05,86.91 75.05,85.97 74.21,85.14 71.31,85.14 70.8,85.65 70.8,87.32
  vias: v1(57.19,88.34) v1(57.19,87.65) v1(57.24,91.89) v1(57.78,90.57) v1(57.79,89.93) v1(57.99,92.57) v1(57.95,87.68) v1(58,91.92) v1(58.36,88.34) v1(58.89,90.6) v1(58.9,89.96) v1(59.09,92.55) v1(59.05,87.66) v1(59.1,91.91) v1(59.32,88.34) v1(60.28,92.55) v1(60.29,91.91) v1(60.23,88.31) v1(60.24,87.67) v1(61.38,92.54) v1(61.39,91.89) v1(61.37,91.11) v1(61.38,90.47) v1(61.39,89.69) v1(61.33,88.29) v1(61.34,87.65) v1(61.4,89.04) v1(62.35,92.56) v1(62.36,91.92) v1(62.38,91.11) v1(62.39,90.47) v1(62.41,89.69) v1(62.42,89.04) v1(62.45,88.39) v1(62.45,87.63) v1(63.25,92.57) v1(63.26,91.92) v1(63.26,91.2) v1(63.27,90.56) v1(63.29,89.78) v1(63.29,88.36) v1(63.3,89.13) v1(63.3,87.71) v1(64.19,92.59) v1(64.22,91.57) v1(64.21,90.73) v1(64.25,89.72) v1(64.24,88.73) v1(64.28,87.71) v1(65.29,92.57) v1(65.32,91.56) v1(65.31,90.71) v1(65.34,89.7) v1(65.34,88.71) v1(65.37,87.7) v1(66.22,92.59) v1(66.26,91.57) v1(66.24,90.73) v1(66.28,89.72) v1(66.27,88.73) v1(66.31,87.71) v1(67.32,92.57) v1(67.35,91.56) v1(67.34,90.71) v1(67.37,89.7) v1(67.37,88.71) v1(68.22,92.58) v1(68.25,91.56) v1(68.24,90.72) v1(68.27,89.7) v1(68.27,88.72) v1(69.31,92.56) v1(69.35,91.54) v1(69.33,90.7) v1(69.37,89.69) v1(69.36,88.7) v1(70.32,90.67) v1(70.38,89.69) v1(70.38,88.7) v1(71.34,90.55) v1(71.4,89.69) v1(71.39,88.7) v1(72.23,89.66) v1(72.28,88.7) v1(73.12,88.64)
NETPAD24_1: length 7.5
  BOTTOM w0.508: 59.93,52.85 60.49,53.16 60.72,53.62 59.25,56.49 58.36,56.54 58.01,56.44 57.88,56.38 56.91,56.13 R41.1
  vias: v1(55.97,53.34) v1(56.16,52.45) v1(56.28,54.23) v1(56.54,51.56) v1(56.66,53.47) v1(56.92,52.79) v1(56.92,50.54) v1(57.05,54.57) v1(57.31,51.9) v1(57.36,49.54) v1(57.43,53.81) v1(57.69,53.04) v1(57.69,50.89) v1(57.75,48.73) v1(58.07,52.28) v1(58.13,49.89) v1(58.2,47.73) v1(58.59,51.35) v1(58.52,49.08) v1(58.61,46.89) v1(58.96,48.08) v1(59.04,50.35) v1(59.05,45.89) v1(59.14,44.87) v1(59.38,47.23) v1(59.42,49.54) v1(59.53,44.06) v1(59.87,48.54) v1(59.82,46.23) v1(59.8,45.18) v1(59.96,43.19) v1(60.28,47.69) v1(60.38,45.46) v1(60.41,42.19) v1(60.73,46.69) v1(60.92,41.1) v1(61.08,45.8) v1(61.18,48.11) v1(61.37,40.1) v1(61.63,47.11) v1(61.66,46.08) v1(62.37,46.4) v1(62.8,45.57) v1(63.25,44.65) v1(63.7,43.65) v1(64.24,42.57) v1(64.61,41.75) v1(64.92,41.06)
NETR1_1: length 2.1
  TOP w0.508: R1.1 R9.2
NETR2_1: length 2
  BOTTOM w0.508: R2.1 R10.2
NETR3_1: length 2.3
  TOP w0.762: R3.1 66.26,114.68 R11.2
NETR4_1: length 2.1
  BOTTOM w0.508: R4.1 R12.2
NETR5_1: length 2.6
  TOP w0.762: R5.1 135.18,64.4 R13.2
NETR9_1: length 2
  TOP w0.508: R9.1 R14.2
NETR10_1: length 2.1
  BOTTOM w0.508: R10.1 R15.2
NETR11_1: length 2.2
  TOP w0.508: R16.2 66.26,119.76 R11.1
NETR12_1: length 2.1
  BOTTOM w0.508: R12.1 R17.2
NETR13_1: length 2.3
  TOP w0.762: R18.2 135.33,69.44 R13.1
NETR14_1: length 2.2
  TOP w0.508: R14.1 R19.2
NETR15_1: length 2
  BOTTOM w0.508: R15.1 R20.2
NETR16_1: length 2
  TOP w0.508: R16.1 R21.2
NETR17_1: length 2
  BOTTOM w0.508: R17.1 R23.2
NETR18_1: length 2.1
  TOP w0.762: R18.1 R22.2
NETR19_1: length 127
  TOP w0.508: R32.2 46.95,114.67 v1(46.95,113.91) ; R19.1 21.05,25.23 21.05,25.13 v1(21.04,25.13)
  VCC02 w0.508: v1(46.95,113.91) 45.05,112.01 33.11,112.01 24.98,103.88 13.36,103.88 9.35,99.35 6.21,91.38 3.11,74.66 3.33,71.27 3.63,63.93 3.64,63.62 3.64,58.53 7.1,47.45 7.1,47.45 7.19,47.17 7.49,46.6 13.96,32.29 15.21,30.34 18.49,27.28 20.71,25.12 v1(21.04,25.13)
NETR20_1: length 128.8
  TOP w0.508: R33.2 44.12,115.23 44.71,114.2 v1(44.67,114.04)
  VCC02 w0.508: v1(22.17,24.01) 20.01,24.01 15.12,28.91 11.93,33.03 11.87,33.16 9.3,40.74 8.38,42.78 6.85,45.75 6.66,46.33 6.39,47.17 5.41,50.33 3.47,56.53 3.36,56.63 2.88,58.19 2.88,63.61 2.87,63.91 2.57,71.23 2.27,75.85 2.26,76.15 5.04,91.18 8.36,99.62 13.03,104.9 24.6,104.9 32.9,113.19 43.18,113.19 44.03,114.04 v1(44.67,114.04)
  BOTTOM w0.508: v1(22.17,24.01) R20.1
NETR21_1: length 1.9
  TOP w0.508: R45.2 R21.1
NETR22_1: length 2.1
  TOP w0.762: R22.1 134.5,79.47 R47.2
NETR23_1: length 2.3
  BOTTOM w0.508: R23.1 R46.2
NETR32_1: length 2.2
  TOP w0.508: R32.1 R43.2
NETR33_1: length 2.2
  TOP w0.508: R44.2 R33.1
NETR57_2: length 3.8
  TOP w0.762: R57.2 v1(28.69,81.35)
  BOTTOM w0.762: R122.1 v1(28.69,81.35)
NETR60_2: length 4.1
  BOTTOM w0.508: R61.2 U1.14
  BOTTOM w0.762: R60.2 R61.2
NETR62_2: length 4.2
  BOTTOM w0.508: R62.2 78.89,124.71 R63.2 77.18,124.44 U3.14
NETR71_1: length 2.3
  BOTTOM w0.762: U4.6 103.21,111.23 R71.1
NETR74_1: length 2.2
  BOTTOM w0.508: 103.08,108.69 R74.1
  BOTTOM w0.762: U4.4 103.08,108.69
NETR76_2: length 3.9
  BOTTOM w0.508: U5.14 128.74,43.81 R77.2 R76.2
NETR80_2: length 2.7
  BOTTOM w0.762: R80.2 116.93,108.69 U4.13
NETR93_2: length 3.4
  TOP w0.762: R94.2 106.62,104.16 107.05,103.73 R140.1 107.96,105.38 R93.2
NETR100_1: length 3.9
  TOP w0.381: R100.1 R106.1 U8.4
NETR104_1: length 2
  TOP w0.381: U8.1 119.97,110.1 R104.1
NETR109_1: length 2.8
  BOTTOM w0.762: U10.6 R109.1
NETR111_1: length 2.8
  BOTTOM w0.762: U10.4 R111.1
NETR114_2: length 2.4
  BOTTOM w0.508: R114.2 20.18,86.05 U10.13
NETR118_1: length 13.4
  TOP w0.762: v1(115.18,23.96) R118_2.1
  BOTTOM w0.508: v1(115.18,23.96) 113.38,21.08 112.76,20.87 110.08,22.07 109.82,22.6 U11.6
  BOTTOM w0.762: R118.1 111.01,25.27 U11.6
NETR120_1: length 19.9
  TOP w0.762: v1(116.17,23.47) R120_2.1
  BOTTOM w0.508: v1(116.17,23.47) 113.88,20.44 112.65,20.01 106.75,22.31 106.5,22.7 106.57,23.41 107.03,23.87 107.66,24.13 U11.4
  BOTTOM w0.762: U11.4 108.93,26.79 R120.1
NETR122_2: length 3.3
  BOTTOM w0.762: R122.2 R124.2 R141.1
NETR123_2: length 5.4
  BOTTOM w0.381: R123.2 100.58,15.55 100.74,15.59 102.18,14.91 103.11,15.25 103.6,15.49 U11.13
NETR129_1: length 4.8
  BOTTOM w0.381: U12.4 77.83,71.69 78.21,72.07
  BOTTOM w0.508: R133.1 78.21,72.07
  BOTTOM w0.762: R133.1 79.42,72.8 78.66,73.57 R129.1
NETR132_1: length 2.1
  BOTTOM w0.305: R132.1 74.66,72.39 75.58,72.39 75.88,72.08 U12.1
NETR135_2: length 11.3
  TOP w0.762: R142.1 96.61,33.13 101.5,31.1 R135.2 103.56,30.53 R136.2
NETRJ0_1: length 41.6
  TOP w1.016: T4.1 86.07,27.81 76.08,37.8 v1(76.08,43.56)
  BOTTOM w1.016: v1(76.08,43.56) 76.08,61.01 77.35,62.29 RJ0.1
NETRJ0_2: length 214.3
  TOP w1.016: T2.1 v1(88.99,118.23)
  TOP w1.27: v1(10.51,57.02) 8.93,57.71 8.59,58.76 T3.1
  VCC02 w1.016: v1(112.54,100) 113.25,100.71 113.25,116.45 109.57,120.14 90.13,120.14 88.99,118.99 v1(88.99,118.23)
  PWM04 w1.016: v1(10.51,57.02) 7.9,60.72 6.19,62.43 6.19,66.69 6.57,67.07 6.57,67.31 9.03,69.76 9.57,75.87 13.8,82.97 21.67,87.26 25.5,87.41 28.46,85.47 32.1,85.47 34,87.37 43.63,87.37 49.55,81.45 57.75,81.45 v1(58.36,82.06)
  BOTTOM w0.381: U12.7 76.53,66.05 76.8,65.78
  BOTTOM w1.016: 84.62,69.44 80.49,65.3 79.61,65.3 RJ0.2 79.37,65.11 79.37,65.15 77.57,65.15 77.19,65.39 76.8,65.78 ; 84.62,69.44 105.32,90.17 105.32,90.19 110.45,95.32 110.45,97.89 111.66,99.09 v1(112.54,100) ; 84.62,69.44 84.62,69.45 78.93,75.15 67.31,75.15 60.39,82.06 v1(58.36,82.06)
NETT1_1: length 8.5
  TOP w0.381: 121.88,104.52 U8.7
  TOP w0.508: T1.1 127.09,103.27 126.41,103.5 124.1,102.48 123.66,102.48 123.29,102.75 121.88,104.52
P_-2.7V: length 76.4
  PWM04 w0.635: J1.20 63.01,130.25 62.56,130.7 40.22,130.7 39.84,130.68 38.76,129.98 37.94,129.15 28.67,118.61 v1(22.89,109.76)
  BOTTOM w0.508: C129.1 23.43,105.72 22.71,105.67 D26.2
  BOTTOM w0.762: v1(22.89,109.76) C47.2 C42.2
  BOTTOM w1.27: C42.2 C46.2 D26.2 CN2.9
PWM-U-H: length 35.7
  BOTTOM w0.508: J2.2 90.16,129.24 89.39,128.48 89.34,125 91.53,122.8 108.82,122.8 R72.1
PWM-U-L: length 110.9
  PWM04 w0.508: J2.4 94.12,129.72 92.14,131.69 46.78,131.69 43.96,133.35 43.16,133.32 41.55,132.39 38.5,131.01 38.05,130.71 36.41,129.03 26.96,118.61 22.19,112.14 21.38,110.39 22.19,107.18 v1(38.03,96.09)
  BOTTOM w0.762: v1(38.03,96.09) 38.87,96.09 39.44,95.52 R67.1
PWM-V-H: length 121.5
  PWM04 w0.508: J2.6 93.43,132.46 47.58,132.46 44.27,134.22 42.99,134.22 39.08,132.47 36.67,130.93 35.89,129.87 35.08,129.08 34.85,128.77 16.74,111.08 10.27,100.65 7.38,93.01 7.42,89.88 v1(11.9,85.72)
  BOTTOM w0.508: R110.1 v1(11.9,85.72)
PWM-V-L: length 238.6
  PWM04 w0.635: v1(59.25,21.59) 41.89,21.56 40.06,20.03 23.92,20.11 16.83,27.2 7.46,43.68 3.75,55.67 1.87,67.68 1.87,75.91 3.42,85.34 6.59,93.28 9.53,101.02 16.09,111.6 34.23,129.31 35.74,131.39 36.79,132.2 38.48,133.11 43.13,135.22 44.67,135.22 48.55,133.3 95.12,133.3 J2.8
  BOTTOM w0.508: v1(59.25,21.59) 66.06,21.59 R86.1
PWM-W-H: length 155.5
  PWM04 w0.508: v1(105.21,9.81) 112.43,14.29 123.73,25.49 131.07,35.38 134.28,42.03 136.01,49.85 139.79,60.96 140.05,63.75 140.13,69.93 139.17,84.22 131.54,103.26 125.01,113.25 112.27,125.94 109.71,127.93 106.91,127.93 105.76,127.96 97.93,127.96 J2.5
  BOTTOM w0.508: v1(105.21,9.81) 105.63,10.03 R119.1
PWM-W-L: length 84.9
  PWM04 w0.381: 108.04,126.74 106.77,125.47 99.79,125.47 99.2,126.06 J2.7
  PWM04 w0.508: 108.04,126.74 109.95,126.74 111.28,125.64 124.4,112.49 125.81,110.51 130.8,102.88 134.6,93.42 135.47,90.31 135.6,88.37 133.65,85.53 130.57,82.37 126.96,81.48 126.54,81.51 124.87,82.45 118.88,88.79 v1(118.52,89.21)
  BOTTOM w0.508: v1(118.52,89.21) 118.35,90.63 R101.1
TEMP: length 30.6
  TOP w0.254: 61.74,129.92 61.74,126.16 61.12,125.54 56.53,125.54 J1.13
  TOP w0.381: NTC1.2 75.28,131.45 62.58,131.45 61.74,130.6 61.74,129.92
U_SAMPLE: length 19
  TOP w0.381: v1(49.24,124.46) 50.45,124.46 53.9,122.1 R45.1 ; J1.4 42.51,129.41 42.51,131.26 R38.2
  VCC02 w0.381: J1.4 43.96,127.96 48.53,127.96 49.04,127.45 49.04,124.66 v1(49.24,124.46)
V_SAMPLE: length 140.4
  TOP w0.381: J1.6 45.23,129.84 48.91,133.53 48.91,134.82 R39.2
  TOP w0.508: v1(17.57,37.64) 10.33,36.87 v1(9.46,37.65) 9.46,37.69 ; v1(47.05,136.65) R39.2
  VCC02 w0.508: v1(47.05,136.65) 43.37,135.47 40,133.69 36.3,131.71 27.86,126.17 21.5,120.74 15.37,113.77 11,107.41 7.47,100.33 7.06,99.55 4.5,92.58 4.29,91.89 3.32,88.41 1.67,78.62 1.33,75.11 1.59,64.03 1.94,59 1.94,58.62 1.99,58.48 2.07,57.68 5.75,45.69 8.78,39.01 v1(9.46,37.65)
  BOTTOM w0.508: R46.1 v1(17.57,37.64)
VA+3.3V: length 289.8
  I_SAMPLING05 w1.27: v1(84.8,126.87) 87.85,123.82 110.8,123.82 111.06,123.57 111.13,123.57 119.57,116.25 125.69,108.29 132.88,95.5 135.86,85.49 137.37,73.8 138.08,69.17 138.09,69.08 136.49,55.47 134,51.02 131.66,48.87 130.09,44.55 126.54,36.35 v1(127.22,35.15) ; v1(18.32,49.46) 12.08,49.16 11.02,49.05 6.56,53.51 4.66,61.98 3.67,67.98 3.55,69.15 4.14,78.1 4.8,83.4 6.79,88.78 12.66,100.2 19.78,108.34 27.78,108.31 31.18,108.3 36.35,114.61 37.71,115.97 40.78,115.97
  BOTTOM w0.508: v1(127.22,35.15) R73.2 ; R59.2 v1(84.8,126.87)
  BOTTOM w0.762: v1(84.8,126.87) 82.87,128.8 78.11,128.8 73.72,133.19 47.06,133.19 44.81,133.19 39.59,133.19 36.39,129.99 36.39,125.6 38.24,123.74 39.84,122.12 ; R58.2 v1(18.32,49.46)
  vias: v1(39.33,114.42) v1(39.72,115.06) v1(39.97,115.82) v1(40.6,116.45)
VA+5V: length 502.2
  TOP w0.762: R83.1 66.39,21.84 65.12,22.22 v1(64.45,23.03) ; R66.1 39.49,93.59 38.32,93.59 ; v1(118.66,91.49) R99.1
  TOP w1.27: C41.1 34.73,96.43 37.56,93.59 38.32,93.59
  VCC02 w1.016: v1(64.45,23.03) 62.5,23.03 60.1,20.63 57.38,17.78 42.51,17.78 39.97,15.85 v1(28.41,15.85) ; v1(96.13,18.82) 96.95,19.53 98.05,19.81 98.82,19.54 106.3,16.46 112.09,16.46 121.77,26.05 121.75,28.52 v1(123.92,30.73)
  PWM04 w0.889: v1(121.12,102.1) 121.25,101.98 121.25,94.08 v1(118.66,91.49)
  PWM04 w1.016: 115.09,117.15 117.19,115.06 117.19,112.26 119.79,109.66 119.79,106.74 121.12,105.41 v1(121.12,102.1)
  PWM04 w1.27: 115.09,117.15 109.21,123.03 89.27,123.03 86.96,125.34 86.96,127.38 85.94,128.39 77.05,128.39 72.35,123.69 52.09,123.69 49.73,121.33 42.31,121.33 C41.1 34.28,107.72 40.58,101.42 40.58,94.26 38.36,92.03 36.07,92.03 33.82,89.78 27.61,89.78 v1(26.14,91.26)
  I_SAMPLING05 w1.016: J1.15 57.93,126.23 56.78,125.09 52.54,125.09 44.54,117.09 44.54,115.82 40.99,112.26 37.05,112.26 35.19,110.41 C41.1
  BOTTOM w0.508: R127.1 v1(96.13,18.82) ; R116.1 v1(26.14,91.26)
  BOTTOM w0.762: R81.1 121.1,102.09 v1(121.12,102.1)
  BOTTOM w1.27: v1(28.41,15.85) 17.98,25.7 13.27,33.24 9.2,41.52 5.26,53.58 4.24,58.51 2.96,70.76 2.51,74.41 2.66,77.74 4.18,86.59 7.55,97.17 16.12,111.75 18.16,113.79 26.38,113.79 27.52,112.64 ; v1(121.12,102.1) 126.5,103.98 130.39,102.73 130.6,102.32 134.9,92.26 136.26,88.48 138.22,82.51 139.16,67.59 136.4,51.31 134.08,44.06 130.27,36.44 128.19,33.14 126.13,30.85 v1(123.92,30.73)
W_SAMPLE: length 125.8
  TOP w0.381: v1(65.37,137.54) 64.53,138.37 57.32,138.37 56.2,137.25 R40.2 56.2,135.35 50.31,129.46 J1.10
  TOP w0.762: v1(84.8,137.54) 90.92,137.54 93.8,137 97.7,135.81 99.18,135.03 102.11,133.83 103.37,133.16 110.63,128.73 120.57,120.57 129.29,109.95 135.26,98.79 136.67,94.87 138.24,89.7 134.19,83.22
  VCC02 w0.508: v1(84.8,137.54) 76.67,137.54 74.77,135.63 67.27,135.63 v1(65.37,137.54)

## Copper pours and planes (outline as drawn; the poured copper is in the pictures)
+15V on TOP: 126.75,109.38 125.06,108.6 124.81,107.94 122.25,106.72 121.72,106.78 121.42,106.6 121.41,106.53 122.18,104.9 122.98,104.49 125.6,105.67 125.63,105.8 125.31,106.53 125.28,106.8 127.51,107.9 127.57,108.15 127,109.33
+15V_L on I_SAMPLING05: 39.56,133.83 41.24,133.52 41.39,133.07 41.34,132.79 41.11,132.63 39.72,132.58 39.23,133.07
-3V_W_H on TOP: 101.59,22.31 101.12,22.56 100.59,24.47 98.83,24.49 98.65,24.71 98.67,25.15 98.66,27.06 97.95,27.42 97.9,27.62 98.41,28.67 98.41,28.67 101,29.08 101.84,28.7 101.84,28.63 101.46,27.81 101.02,27.66 100.32,26.17 100.17,25.84 100.48,25.42 101.2,25.42 101.39,25.21 102.2,22.98 101.9,22.35
AGND on BOTTOM (solid shape): 28.89,41.77 30.13,39.12 29.94,38.61 27.99,37.7 27.82,37.76 26.42,40.75 26.55,41.09 28.39,41.95
AGND on BOTTOM (solid shape): 131.02,50.62 131.77,50.24 131.92,49.76 130.77,47.37 129.65,47.45 129.35,47.34 127.51,48.2 127.33,48.7 128.56,51.35 129.07,51.54
AGND on BOTTOM (solid shape): 73.43,73.97 73.43,71.69 73.56,71.56 75.21,71.56 75.33,71.43 75.33,70.67 75.71,70.29 78.25,70.29 78.38,70.42 78.38,70.67 78.64,70.93 80.92,70.93 81.05,70.8 81.05,68.64 75.71,68.64 75.08,69.27 72.54,69.27 72.29,69.02 70.51,69.02 70.25,69.27 70.25,70.42 70.13,70.54 68.48,70.54 68.35,70.67 68.35,73.97 68.48,74.1 73.3,74.1
AGND on BOTTOM (solid shape): 22.92,92.06 23.7,91.78 24.46,90.13 24.41,89.97 22,88.85 21.7,88.74 21.58,88.78 21.15,89.7 21.12,89.68 21.05,89.82 20.98,89.85 20.78,89.89 20.77,89.92 20.22,90.29 19.78,89.78 19.78,89.43 17.35,88.37 17.35,88.36 16.89,87.92 17.22,87.38 17.65,87.23 17.82,86.88 13.72,84.97 13.66,84.99 12.86,86.69 12.66,87.24 13.05,87.88 22.44,92.2
AGND on BOTTOM (solid shape): 99.05,19.05 99.39,18.89 99.46,18.7 99.06,17.7 98.14,17.05 97.15,15.13 96.74,14.25 96.77,14.17 96.73,14.09 96.82,14.05 96.95,13.67 97.9,13.23 97.89,13.19 98.25,12.5 99.01,12.67 99.03,12.7 99.91,12.29 100.32,12.09 100.33,12.08 100.49,11.96 100.69,11.91 100.7,11.91 100.8,11.86 101.11,12.06 101.39,12.67 101.56,13.05 101.66,13.12 102.45,12.76 102.49,12.86 103.19,12.54 103.14,12.43 104.06,12.01 104.11,12.11 104.47,11.94 104.43,11.83 105.36,11.4 104.88,10.37 103.35,9.66 95.97,13.1 95.97,15.06 97.3,17.55 97.12,18.06 96.64,18.76 96.64,18.82 96.64,19.44 96.91,20.03
AGND on TOP: 128.12,106.72 125.97,105.74 125.79,105.8 125.47,106.5 125.47,106.75 127.56,107.76 127.59,107.76 127.85,107.88 127.85,108.2 126.2,110.74 125.95,110.87 125.19,112.52 126.1,112.06 127.06,110.99 128.87,108.32 128.87,107.54 128.62,107.15
AGND on TOP: 116.63,104.8 118.46,105.65 118.71,105.66 118.84,105.53 119.22,105.53 119.34,105.66 119.34,105.79 119.34,106.05 124.53,108.45 124.51,109.98 126.04,110.7 126.11,110.9 125.6,112.04 125.6,112.04 125.2,112.45 121.88,113.78 120.2,113.03 120.18,112.96 120.6,112.1 121.93,111.37 122.44,110.3 122.31,110.03 121.16,109.48 120.79,108.54 118.77,107.6 117.63,107.83 116.59,107.36 116.17,105.72
AGND on TOP: 40.35,93.21 40.35,94.99 40.73,95.37 42.76,95.37 42.89,95.25 42.89,93.47 42.64,93.21
AGND on BOTTOM: 118.46,115.41 120.16,115.41 120.78,114.79 120.78,111.5 120.23,110.99 118.58,110.99 118.33,111.18 118.33,115.28
AGND on BOTTOM: 25.93,95.32 23.61,96.67 23.26,97.87 24.46,99.13 25.83,99.29 28.37,97.76 31.27,97.13 32.26,98.57 32.59,98.73 33.08,99.42 33.25,99.69 33.23,99.77 33.14,100.63 27.71,104.5 27.63,105.02 31.39,110 31.76,110.11 33.83,108.67 34.02,108.74 35.42,109.16 35.42,109.16 36.52,110.87 37.51,112.29 37.38,112.51 36.98,113.36 37.51,114.08 38.96,113.14 39.79,112.74 40.14,112.8 41.12,114.13 41.2,114.24 41.61,114.34 41.62,114.34 42.72,113.55 42.74,112.94 41.07,110.6 40.7,110.19 39.63,108.62 39.64,108.58 39.66,108.36 40.02,106.68 32.47,95.12 31.22,94.54
AGND on BOTTOM: 114.81,86.81 115.36,87.99 115.74,88.11 115.81,88.16 116.21,89.05 116.27,89.08 118.51,88.11 118.72,88.01 118.91,87.24 118.23,85.7 118.07,85.34 117.62,85.23 114.93,86.48
AGND on BOTTOM: 118.32,103.5 118.33,106.17 118.46,106.29 119.46,106.29 119.98,106.8 120.49,106.8 120.74,106.55 120.74,105.79 120.61,105.53 120.61,104.39 120.36,104.14 120.36,103.25 120.11,102.99 118.58,102.99 118.32,103.25
AGND on BOTTOM: 70.7,123.31 71.85,123.31 72.86,124.58 73.12,124.58 73.37,124.33 73.55,123.26 73.75,123.06 73.75,121.03 73.37,120.65 70.7,120.65 70.45,120.9 70.45,123.06
AGND on BOTTOM: 40.32,94.56 40.86,95.32 40.94,95.45 44.12,95.45 44.41,94.97 44.41,93.37 44.11,93.09 43.43,93.09 43.25,93.21 40.54,93.22 40.32,93.4
AGND on GND03: outline of 95 points within 1.26,0.51 140.82,138.17 ; 2 cut-outs
AGND on I_SAMPLING05: 68.9,75.79 67.22,74.11 67.22,64.79 69.23,62.78 76.62,62.78 78.32,61.08 80.79,61.08 82.06,62.35 82.06,62.38 82.39,62.71 82.39,72.67 79.26,75.79
P6.5V on BOTTOM: 19.86,101.16 19.42,100.69 18.76,100.69 16.74,102.7 16.74,108.05 19.9,112.38 20.18,112.66 22.27,112.66 24.66,110.99 27.92,107.72 27.92,107.07 26.8,105.65 26.79,105.64 26.21,105.64 23.47,107.62 23.47,110.16 22.95,110.67 21.67,111.5 21.41,111.5 21.28,111.38 18.73,107.53 18.73,103.46 19.61,102.69 19.87,102.26
(no net) on BOTTOM: 105.36,11.52 101.77,13.2 101.56,13.05 101.39,12.67 101.11,12.06 100.8,11.86 99.91,12.29 96.95,13.67 96.74,14.25 97.15,15.13 98.14,17.05 99.06,17.7 99.46,18.7 99.39,18.89 99.05,19.05 96.89,20.04 96.64,19.5 96.47,19.09 96.51,18.94 97.12,18.06 97.3,17.55 95.97,15.06 95.97,13.1 103.35,9.66 104.88,10.37 105.39,11.46
(no net) on BOTTOM: 13.72,84.97 17.98,86.95 18.03,87.11 17.43,88.4 20.81,89.88 20.98,89.85 21.05,89.82 21.53,88.8 21.7,88.74 22,88.85 24.41,89.97 24.46,90.13 23.7,91.78 22.92,92.06 22.44,92.2 13.05,87.88 12.66,87.24 12.86,86.69 13.66,84.99
(no net) on BOTTOM: 128.56,51.35 129.07,51.54 131.02,50.62 131.77,50.24 131.92,49.76 130.77,47.37 129.65,47.45 129.35,47.34 127.51,48.2 127.33,48.7
(no net) on BOTTOM: 127.8,41.19 129.87,40.22 129.93,40.05 129.61,39.36 129.44,39.3 129.03,39.49 128.23,39.49 127.22,37.46 126.76,37.23 126.58,37.32 124.3,41.9 125.35,44.16 125.69,44.28 127.64,43.37 127.77,43.03 127.34,42.11 127.46,41.78
(no net) on BOTTOM: 30.13,39.12 29.94,38.61 27.99,37.7 27.82,37.76 26.42,40.75 26.55,41.09 28.39,41.95 28.89,41.77
(no net) on BOTTOM: 22.83,46.24 20.76,45.27 20.59,45.33 20.27,46.02 20.33,46.19 21.14,46.57 21.38,47.24 19.93,50.35 20.06,50.69 20.97,51.11 25.1,49.61 26.69,46.2 26.56,45.86 24.61,44.95 24.27,45.07 23.84,46 23.5,46.12
CLAMP_U_L on BOTTOM: 55.28,88.06 54.93,87.71 54.93,85.27 54.67,85.01 51.6,85.01 51.31,85.3 51.31,90.99 50.4,91.9 48.62,91.9 48.34,92.18 48.34,92.52 48.53,92.71 48.53,92.71 52.7,92.71 53.11,92.29 54.83,92.29 55.32,91.8
CLAMP_V_L on BOTTOM: 65.61,39.2 66.09,39.03 66.13,38.98 68.42,40.01 68.64,39.93 69.8,37.45 69.69,37.08 65.24,35.05 64.64,34.36 64.2,33.15 64.96,31.54 64.82,31.16 64.51,31.02 64.26,31.11 64.26,31.12 62.5,34.89 62.7,35.44 61.98,37 62.19,37.59
CLAMP_W_L on BOTTOM: 103,80.49 102.97,80.58 104.27,83.37 104.48,83.44 108.3,81.53 108.71,81.61 109.8,81.1 111.01,81.55 111.77,83.16 112.14,83.3 112.45,83.15 112.54,82.9 112.53,82.9 110.77,79.12 110.22,78.92 109.49,77.36 109.06,77.2 105.76,78.75 105.25,79.37
DRV_U_H on BOTTOM: 97.63,113.45 103.31,113.45 103.92,112.84 106.44,112.84 106.51,112.77 106.51,112.21 106.4,112.1 101.29,112.1 101,111.81 101,108.05 100.04,107.1 97.8,107.1 97.23,107.67 97.25,110.74 97.5,111.12 97.5,113.3
DRV_V_H on BOTTOM: 24.18,66.9 21.7,72.1 21.86,72.53 20.79,74.81 20.82,74.91 21.33,75.15 21.48,75.09 23.65,70.46 23.71,70.33 23.89,70.25 27.56,71.92 27.9,71.75 28.67,69.97 30.16,69.96 30.52,69.21 30.52,69.01 27.83,67.76 27.64,67.82 27.24,67.86 24.88,66.8
